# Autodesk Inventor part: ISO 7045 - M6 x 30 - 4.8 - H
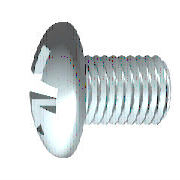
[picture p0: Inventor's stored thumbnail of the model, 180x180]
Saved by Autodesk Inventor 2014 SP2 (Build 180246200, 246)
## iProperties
Created: 2013-02
Part Number: ISO 7045 - M6 x 30 - 4.8 - H
Material: Stainless Steel, 440C
Description: Pan head screw with type H cross recess - product grade A
Document SubType Name: Modeling
Standard: ISO 7045
Designer: SFC
Standard Revision: Second edition 1994-04-01
Standards Organization: ISO
Language: en-US
Size Designation: M6 x 30 - 4.8 - H
Categories: <MemberInstance><Categories><Category DisplayName="Fasteners" InternalName="e4da775c-781d-43d5-af7c-5136215cf5a6" Mnemonic="FSTN"><Category DisplayName="Bolts"
Density: 7.75 g/cm^3
Appearance: Semi-Polished
IsCustomPart: 0
Author: SFC
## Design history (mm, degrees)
body "Solid1"
workplane "Work Plane3"
sketch "Sketch2"
  geometry: L1 (-8.27, 0)-(8.27, 0) reference; L2 (0, -8.27)-(0, 8.27) reference; L3 (0, 3.45)-(0, 0); L4 (0, 0)-(3.45, 0); L5 (0, 0)-(4.177, 4.177); L6 (1, 3.302)-(0.636, 1.026); L7 (3.302, 1)-(1.026, 0.636); L8 (1, -3.302)-(0.636, -1.026); L9 (3.302, -1)-(1.026, -0.636); L10 (-1, 3.302)-(-0.636, 1.026); L11 (-3.302, 1)-(-1.026, 0.636); L12 (-3.302, -1)-(-1.026, -0.636); L13 (-1, -3.302)-(-0.636, -1.026); A1 r 1.035 centre (0, 0) between (1.035, 0) and (0, 1.035); A2 r 3.45 centre (0, 0) between (3.45, 0) and (3.302, 1); A3 r 3.45 centre (0, 0) between (1, 3.302) and (0, 3.45); A4 r 3.45 centre (0, 0) between (3.302, 1) and (1, 3.302); A5 r 3.45 centre (0, 0) between (0, -3.45) and (1, -3.302); A6 r 3.45 centre (0, 0) between (1, -3.302) and (3.302, -1); A7 r 3.45 centre (0, 0) between (3.302, -1) and (3.45, 0); A8 r 3.45 centre (0, 0) between (-3.302, 1) and (-3.45, 0); A9 r 3.45 centre (0, 0) between (-1, 3.302) and (-3.302, 1); A10 r 3.45 centre (0, 0) between (0, 3.45) and (-1, 3.302); A11 r 3.45 centre (0, 0) between (-3.45, 0) and (-3.302, -1); A12 r 3.45 centre (0, 0) between (-3.302, -1) and (-1, -3.302); A13 r 3.45 centre (0, 0) between (-1, -3.302) and (0, -3.45); A14 r 1.208 centre (0, 0) between (1.208, 0) and (0, 1.208); A15 r 0.34 centre (0.972, 0.972) between (0.636, 1.026) and (1.026, 0.636); A16 r 0.34 centre (0.972, -0.972) between (1.026, -0.636) and (0.636, -1.026); A17 r 0.34 centre (-0.972, 0.972) between (-1.026, 0.636) and (-0.636, 1.026); A18 r 0.34 centre (-0.972, -0.972) between (-0.636, -1.026) and (-1.026, -0.636); 1 further point
  constraints: 38 point on circle, 22 end point, 19 symmetric about line, 18 centre point, 4 coincident, 3 collinear, 3 point on line, 3 tangent, 1 perpendicular, 21 other
  dimensions: "d4" = 45 deg angle of L5 L4; "d5" = 2.07 diameter of A1 (= 0.3 x SDM); "d6" = 6.9 diameter of A4 (= SDM); "d7" = 1 distance from line of L6.start L3 (= 0.5 x SBR); "d14" = 2.415 diameter of A14 (= 0.35 x SDM)
extrude "Slot" join sketch "Sketch2" taper "d15" = 5 deg; stored distance "d54" = 10
revolve "Cut" stored, may be unused: angle "d56" = 90 deg
revolve "Body" stored, may be unused: angle "d18" = 90 deg
sketch "Sketch1"
  geometry: L1 (30, 0)-(30, 3); L2 (30, 3)-(2, 3); L3 (3.962, 5.08)-(3.962, 5.08); L4 (-4.6, 0)-(-4.6, 5.839); L5 (-4.078, 3.19)-(-2.197, 2.252); L6 (-2.197, 2.252)-(-1, 0); L7 (-1, 0)-(30, 0); L8 (-12.085, 0)-(37.014, 0) reference; L9 (0, -1.212)-(0, 7.273) reference; L10 (-4.078, 3.19)-(-4.6, 3.45); L11 (-2.669, 5.907)-(-4.6, 5.839); L12 (-2.669, 5.907)-(0, 6); L13 (0, 6)-(0, 2.729); L14 (0, 2.729)-(1.387, 2.729); L15 (1.387, 2.729)-(2, 3); L16 (2, 3)-(0, 3); A1 r 10 centre (5.4, 0) between (-2.669, 5.907) and (-4.6, 0)
  constraints: 28 end point, 5 point on line, 4 collinear, 4 point on circle, 3 parallel, 2 perpendicular, 1 centre point, 1 horizontal, 1 tangent
  dimensions: "d1" = 6 diameter of L2 L7 (= GD); "d2" = 3.6 distance from line of L6.end L4 (= STI); "d11" = 6.9 diameter of L10.end L7 (= SDM); "d12" = 62 deg angle of L6 L7; "d13" = 26.5 deg angle of L5 L7; "d17" = 12 diameter of L12.end L7 (= KOD); "d19" = 2 deg angle of L12 L7 (= KEWI); "d20" = 4.6 distance between parallel lines of L4 L13 (= KOH); "d21" = 10 radius of A1 (= KR); "d23" = 5.45873 diameter of L14 L7 (= BDM); "d24" = 28 distance of L1.end L2.end (= GEL); "d25" = 0.61345 horizontal distance of L14.end L2.end (= GAL); "d28" = 30 distance between parallel lines of L1 L13 (= NLG)
workplane "Work Plane1"
fillet "Fillet1" dims "d29" = 2 (= RR)
fillet "Fillet2" dims "d16" = 0.4 (= 0.2 x SBR)
feature "Thread" dims "d8" = 28 (= GEL), "d9" = 0
chamfer "Chamfer1" distance "d26" = 0.61345 (= -0.5 x SPD + 0.5 x GD); stored, may be unused: second distance "d27" = 0.61355 (computed from GUL), angle "d78" = 45 deg
other parameters: "GD" = 6 [user parameter; used in 2 equation terms], "NLG" = 30 [user parameter; used in 1 equation term], "GEL" = 28 [user parameter; used in 2 equation terms], "KOD" = 12 [user parameter; used in 1 equation term], "KOH" = 4.6 [user parameter; used in 2 equation terms], "SDM" = 6.9 [user parameter; used in 4 equation terms], "STI" = 3.6 [user parameter; used in 1 equation term], "SBR" = 2 [user parameter; used in 2 equation terms], "GAL" = 0.61345 (= 0.61345 x PTC) [user parameter; used in 1 equation term], "SPD" = 4.7731 (= NND - 1.2269 x PTC) [user parameter; used in 1 equation term], "KEWI" = 2 deg [user parameter; used in 1 equation term], "d3" = -4.6 (= -KOH), "d10" = 0, "KR" = 10 [user parameter; used in 1 equation term], "BDM" = 5.45873 [user parameter; used in 1 equation term], "GUL" = 0.61345 (= 0.61345 x PTC) [user parameter; used in 1 equation term], "RR" = 2 [user parameter; used in 1 equation term], "d79" = 0, "d80" = 0, "PTC" = 1 [user parameter; used in 5 equation terms], "THREADDIA" = 6 [user parameter; used in 1 equation term], "TOA" = 30 deg [user parameter], "NND" = 6 [user parameter; used in 1 equation term], "GD1" = 4.7731 (= THREADDIA - 1.2269 x PTC) [user parameter]
